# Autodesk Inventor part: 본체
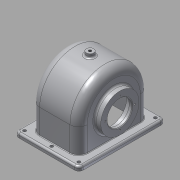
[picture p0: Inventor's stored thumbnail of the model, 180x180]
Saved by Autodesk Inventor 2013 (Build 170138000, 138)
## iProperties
Created: 2015-09
Part Number: 본체
Material: 알루미늄 6061
Document SubType Name: Modeling
Designer: user-11
Density: 2.71 g/cm^3
Mass: 656.548 g
Surface Area: 907.988 cm^2
Volume: 242.268 cm^3
Author: user-11
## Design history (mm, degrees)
sketch "스케치2"
  geometry: L1 (-70, 0)-(70, 0) reference; L2 (70, 0)-(-70, 0) reference; L3 (-57, 47)-(-57, 0); L4 (57, 47)-(57, 0); A1 r 57 centre (0, 47) between (57, 47) and (-57, 47); 4 further points
  constraints: 4 end point, 4 point on line, 3 point on circle, 2 perpendicular, 2 tangent, 1 centre point
  dimensions: "d7" = 114 diameter of A1; "d9" = 0 horizontal distance of point (0, 0) A1.centre; "d10" = 47 distance from line of L1 A1.centre
extrude "돌출2" join sketch "스케치2" stored distance "d11" = 77; taper "d12" = 0 deg
fillet "모깎기1" dims "d13" = 14
sketch "스케치4"
  geometry: C1 r 43 at (0, 0) reference; C2 r 31 at (0, 0); 1 further point
  constraints: 1 centre point, 1 coincident
  dimensions: "d15" = 62 diameter of C2
extrude "돌출3" join sketch "스케치4" distance "d17" = 10; taper "d18" = 0 deg
feature "쉘1" dims "d33" = 5
node "작업 평면1"
sketch "스케치3"
  geometry: L1 (51.504, 47)-(-69.611, 47); L2 (38.5, 90)-(38.5, 47) reference; L3 (24.5, 104)-(-24.5, 104) reference; L4 (-38.5, 47)-(-38.5, 90) reference; L5 (38.5, 86.094)-(31.237, 80); L6 (31.237, 80)-(35.5, 80); L7 (35.5, 80)-(35.5, 67); L8 (35.5, 67)-(17.5, 67); L9 (17.5, 67)-(17.5, 75); L10 (17.5, 75)-(33.5, 88.426); L11 (33.5, 88.426)-(33.5, 98); L12 (33.5, 98)-(-33.5, 98); L13 (-33.5, 98)-(-33.5, 67); L14 (-48.5, 78)-(-48.5, 16) reference; L15 (-38.5, 16)-(-38.5, 78) reference; L16 (-33.5, 67)-(-48.5, 67); L17 (-48.5, 47)-(38.5, 47); A1 r 14 centre (24.5, 90) between (38.5, 90) and (24.5, 104) reference; A2 r 14 centre (-24.5, 90) between (-24.5, 104) and (-38.5, 90) reference; 1 further point
  constraints: 24 end point, 6 perpendicular, 4 point on line, 3 parallel, 1 horizontal, 1 midpoint
  dimensions: "d14" = 47 distance from line of point (0, 0) L1; "d19" = 56 diameter of L9.end L1; "d21" = 66 diameter of L5.end L1; "d22" = 50 deg angle of L9 L10; "d23" = 16 distance between parallel lines of L9 L11; "d25" = 40 diameter of L16 L1; "d26" = 5 distance between parallel lines of L4 L13; "d27" = 5 distance between parallel lines of L5 L10; "d28" = 84 distance between parallel lines of L14 L7; "d29" = 40 diameter of L8 L1; "d30" = 6 distance between parallel lines of L3 L12; "d31" = 67 distance between parallel lines of L13 L11
  node "투영된 루프1"
sketch "스케치5"
  geometry: L1 (-27.5, 13)-(76.5, 13); L2 (76.5, 13)-(76.5, -127); L3 (76.5, -127)-(-27.5, -127); L4 (-27.5, -127)-(-27.5, 13); L5 (49, -114)-(0, -114) reference; L6 (-9, -100)-(-9, -14) reference; L7 (58, -14)-(58, -100) reference; L8 (63, -14)-(63, -100) reference; L9 (49, 0)-(0, 0) reference; L10 (-14, -100)-(-14, -14) reference; L11 (49, -114)-(0, -114) reference; L12 (49, -109)-(0, -109) reference; L13 (0, -5)-(49, -5) reference; A1 r 14 centre (49, -100) between (49, -114) and (63, -100) reference; A2 r 14 centre (49, -14) between (63, -14) and (49, 0) reference; A3 r 14 centre (0, -14) between (0, 0) and (-14, -14) reference; A4 r 14 centre (0, -100) between (-14, -100) and (0, -114) reference; A5 r 9 centre (49, -100) between (49, -109) and (58, -100) reference; A6 r 9 centre (0, -100) between (-9, -100) and (0, -109) reference; A7 r 9 centre (0, -14) between (0, -5) and (-9, -14) reference; A8 r 9 centre (49, -14) between (58, -14) and (49, -5) reference; 1 further point
  constraints: 8 end point, 2 parallel, 1 horizontal, 1 perpendicular
  dimensions: "d35" = 104 distance of L1.start L1.end; "d37" = 140 distance of L1.end L2.end; "d38" = 52 distance from line of point (24.5, -57) L4; "d39" = 70 distance from line of point (24.5, -57) L1
extrude "돌출4" join sketch "스케치5" distance "d40" = 7; taper "d41" = 0 deg
sketch "스케치6"
  geometry: 1 further point
sketch "스케치7"
  geometry: C1 r 31 at (0, 0) reference; C2 r 20 at (0, 0); 1 further point
  constraints: 1 centre point, 1 coincident
  dimensions: "d42" = 40 diameter of C2
extrude "돌출5" cut sketch "스케치7" stored distance "d44" = 102; taper "d45" = 0 deg
sketch "스케치8"
  geometry: L1 (38.5, 90)-(38.5, 47) reference; L2 (24.5, 47)-(-24.5, 47) reference; L3 (38.5, 47)-(-31.997, 47); L4 (38.5, 86.094)-(31.237, 80); L5 (31.237, 80)-(33.5, 80); L6 (33.5, 80)-(33.5, 67); L7 (33.5, 67)-(17.5, 67); L8 (17.5, 67)-(17.5, 75); L9 (17.5, 75)-(33.336, 88.288); L10 (33.5, 90)-(33.5, 47) reference; L11 (24.5, 47)-(33.5, 47) reference; L12 (24.5, 47)-(24.5, 47) reference; L13 (24.5, 47)-(33.5, 47) reference; L14 (33.5, 47)-(33.5, 47) reference; L15 (-33.5, 21)-(-33.5, 73) reference; L16 (38.5, 86.094)-(38.5, 88.288); L17 (33.336, 88.288)-(38.5, 88.288); A1 r 9 centre (24.5, 90) between (33.5, 90) and (24.5, 99) reference; 1 further point
  constraints: 18 end point, 4 parallel, 3 point on line, 2 perpendicular, 1 collinear, 1 point on circle
  dimensions: "d46" = 50 deg angle of L8 L9; "d47" = 5 distance between parallel lines of L9 L4; "d49" = 56 diameter of L8.end L3; "d50" = 66 diameter of L5 L3; "d52" = 40 diameter of L7 L3; "d53" = 67 distance between parallel lines of L15 L10 (derived); "d54" = 16 distance between parallel lines of L10 L8
revolve "회전2" sketch "스케치8" stored, may be unused: angle "d55" = 90 deg
sketch "스케치9"
  geometry: L1 (38.5, 90)-(38.5, 47) reference; L2 (37.541, 47)-(3.174, 47); L3 (33.5, 80)-(35.5, 80); L4 (35.5, 80)-(35.5, 67); L5 (17.5, 67)-(38.5, 67) reference; L6 (17.5, 75)-(33.336, 88.288) reference; L7 (33.5, 80)-(38.5, 84.195); 1 further point
  constraints: 8 end point, 3 perpendicular, 2 parallel, 2 point on line
  dimensions: "d56" = 47 distance from line of point (0, 0) L2; "d57" = 3 distance between parallel lines of L1 L4; "d59" = 66 diameter of L3 L2; "d60" = 5 horizontal distance of L7.end L3.start
revolve "회전3" sketch "스케치9" stored, may be unused: angle "d61" = 90 deg
fillet "모깎기2" dims "d62" = 7
fillet "모깎기3" dims "d63" = 1
sketch "스케치11"
  geometry: L1 (-69.5, -127)-(20.5, -127) reference; L2 (20.5, 13)-(-69.5, 13) reference; L3 (27.5, -120)-(27.5, 6) reference; C1 r 2.5 at (-24.5, 5); C2 r 2.5 at (-24.5, -119); 1 further point
  constraints: 2 centre point
  dimensions: "d73" = 5 diameter of C2; "d74" = 5 diameter of C1; "d75" = 8 distance from line of L2 C1.centre; "d76" = 8 distance from line of L1 C2.centre; "d79" = 52 distance from line of L3 C2.centre; "d80" = 52 distance from line of L3 C1.centre
extrude "돌출7" cut sketch "스케치11" stored distance "d77" = 102; taper "d78" = 0 deg
fillet "모깎기4" dims "d87" = 3
fillet "모깎기5" dims "d88" = 3
node "작업 평면2"
sketch "스케치12"
  geometry: C1 r 6 at (45, -70); 1 further point
  constraints: 1 centre point, 1 coincident
  dimensions: "d91" = 12 diameter of C1
extrude "돌출8" join sketch "스케치12" stored distance "d93" = 102; taper "d94" = 0 deg
sketch "스케치13"
  geometry: C1 r 20 at (0, 0) reference; 2 further points
  dimensions: "d95" = 24 distance of C1.centre point (-24, 0); "d96" = 0 vertical distance of C1.centre point (-24, 0)
hole "구멍1" sketch "스케치13" at (-24, 0) diameter "d97" = 2.459; stored, may be unused: countersink angle "d101" = 90 deg, drill point angle "d103" = 118 deg; dims "d98" = 6, "d99" = 4, "d100" = 2, "d102" = 8
sketch "스케치14"
  geometry: C1 r 20 at (0, 0) reference; C2 r 33 at (0, 0) reference; 1 further point
extrude "돌출9" cut sketch "스케치14" distance "d104" = 3; taper "d105" = 0 deg
sketch "스케치15"
  geometry: C1 r 20 at (0, 0) reference; C2 r 33 at (0, 0) reference; 1 further point
fillet "모깎기7" dims "d106" = 0.5
sketch "스케치16"
  geometry: C1 r 20 at (0, 0) reference; 2 further points
  dimensions: "d108" = 28 distance of C1.centre point (0, 28); "d109" = 0 horizontal distance of C1.centre point (0, 28)
hole "구멍2" sketch "스케치16" at (0, 28) diameter "d110" = 2.459; stored, may be unused: countersink angle "d114" = 90 deg, drill point angle "d116" = 118 deg; dims "d111" = 7, "d112" = 4, "d113" = 2, "d115" = 9
fillet "모깎기8" dims "d120" = 3
sketch "스케치17"
  geometry: C1 r 6 at (0, 0) reference; 1 further point
  constraints: 1 coincident
hole "구멍3" sketch "스케치17" at (0, 0) diameter "d121" = 4.459; stored, may be unused: countersink angle "d125" = 90 deg, drill point angle "d127" = 118 deg; dims "d122" = 7, "d123" = 4, "d124" = 2, "d126" = 9
chamfer "모따기1" distance "d128" = 1; stored, may be unused: second distance "d129" = 2, angle "d130" = 45 deg
node "솔리드1"
pattern_linear "직사각형 패턴1" dims "d83" = 44
pattern_linear "직사각형 패턴2" dims "d86" = 44
pattern_circular "원형 패턴1" dims angle "d118" = 360 deg
pattern_circular "원형 패턴2" dims angle "d132" = 360 deg
node "투영된 루프2"
node "투영된 루프3"
other parameters: "d34" = -7
